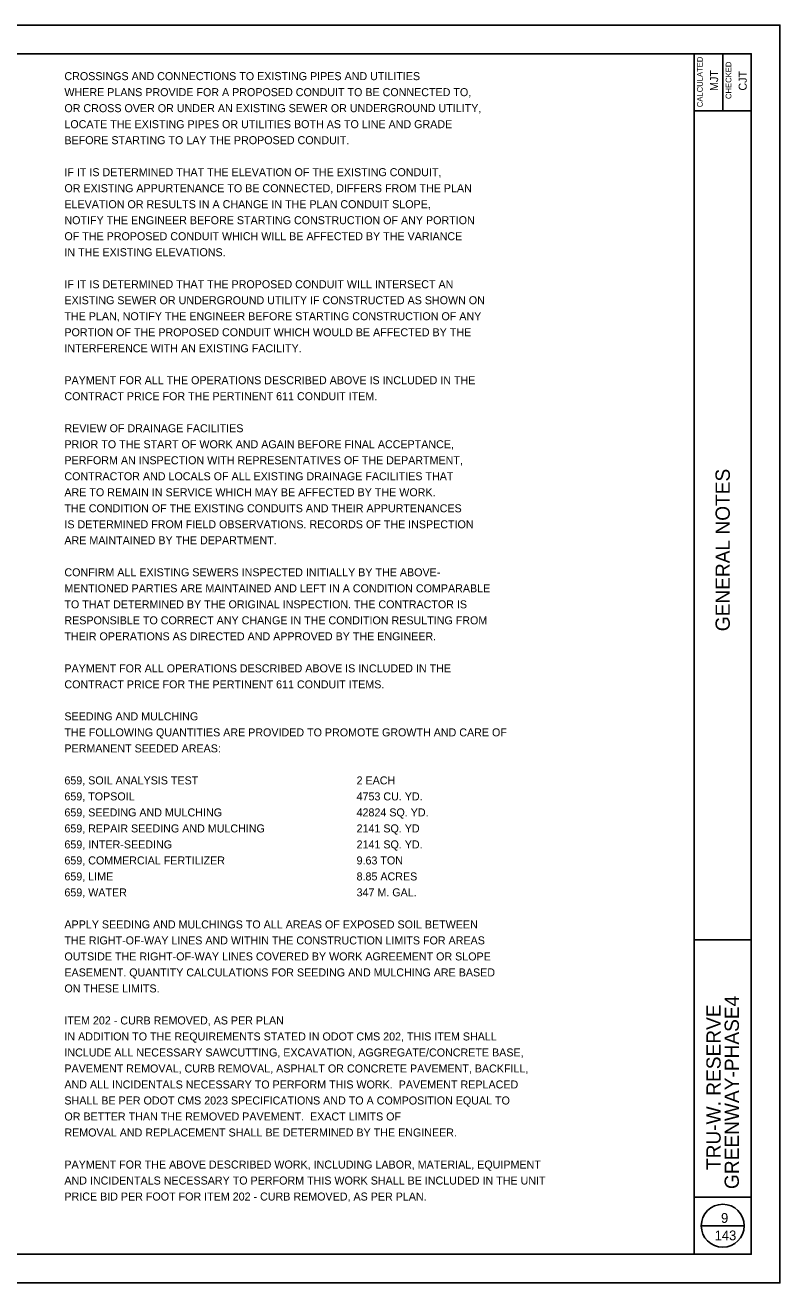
# Model space of a CAD drawing. Extents: x -16 to 195, y -13 to 9.
# Drawn here: x 4.43 to 17.63, y -12.91 to 9.09 of the extents above; entities that cross this region are included whole.
import ezdxf

# ---------------------------------------------------------------- set-up
doc = ezdxf.new("R2010")
doc.units = 0
for name, color, linetype in [('SH_Border', 7, 'Continuous'), ('SH_Cut_Line', 7, 'Continuous'), ('SH_Data', 7, 'Continuous'), ('TX_P_1', 7, 'Continuous')]:
    doc.layers.add(name, color=color, linetype=linetype)

msp = doc.modelspace()

# ---------------------------------------------------------------- linework, layer by layer
at = {"layer": 'SH_Border'}
for p, q in [((16.129, -12.407), (16.129, 8.593)), ((16.629, 8.593), (16.629, 7.593)), ((16.129, 7.593), (17.129, 7.593)), ((16.129, -6.907), (17.129, -6.907)), ((16.129, -11.407), (17.129, -11.407))]:
    msp.add_line(p, q, dxfattribs=at)
msp.add_lwpolyline([(-14.371, 8.593), (17.129, 8.593), (17.129, -12.407), (-14.371, -12.407)], close=True, dxfattribs=at)
at = {"layer": 'SH_Cut_Line'}
msp.add_lwpolyline([(-16.371, -12.907), (17.629, -12.907), (17.629, 9.093), (-16.371, 9.093)], close=True, dxfattribs=at)
at = {"layer": 'SH_Data'}
msp.add_line((16.254, -11.907), (17.004, -11.907), dxfattribs=at)
msp.add_circle((16.629, -11.907), 0.375, dxfattribs=at)

# ---------------------------------------------------------------- texts
for s, height, p in [('CALCULATED', 0.1, (16.281, 7.658)), ('CHECKED', 0.1, (16.781, 7.801)), ('MJT', 0.14, (16.549, 7.942)), ('CJT', 0.14, (17.049, 7.949)), ('GENERAL NOTES', 0.25, (16.754, -1.509)), ('GREENWAY-PHASE4', 0.25, (16.913, -11.266)), ('TRU-W. RESERVE', 0.25, (16.594, -10.934))]:
    msp.add_text(s, height=height, rotation=90, dxfattribs=at).set_placement(p)
for s, p in [('9', (16.6, -11.857)), ('143', (16.488, -12.162))]:
    msp.add_text(s, height=0.17, dxfattribs=at).set_placement(p)
at = {"layer": 'TX_P_1'}
for s, p in [('CROSSINGS AND CONNECTIONS TO EXISTING PIPES AND UTILITIES', (5.116, 8.131)), ('WHERE PLANS PROVIDE FOR A PROPOSED CONDUIT TO BE CONNECTED TO,', (5.116, 7.851)), ('OR CROSS OVER OR UNDER AN EXISTING SEWER OR UNDERGROUND UTILITY,', (5.116, 7.571)), ('LOCATE THE EXISTING PIPES OR UTILITIES BOTH AS TO LINE AND GRADE', (5.116, 7.291)), ('BEFORE STARTING TO LAY THE PROPOSED CONDUIT.', (5.116, 7.011)), ('IF IT IS DETERMINED THAT THE ELEVATION OF THE EXISTING CONDUIT,', (5.116, 6.451)), ('OR EXISTING APPURTENANCE TO BE CONNECTED, DIFFERS FROM THE PLAN', (5.116, 6.171)), ('ELEVATION OR RESULTS IN A CHANGE IN THE PLAN CONDUIT SLOPE,', (5.116, 5.891)), ('NOTIFY THE ENGINEER BEFORE STARTING CONSTRUCTION OF ANY PORTION', (5.116, 5.611)), ('OF THE PROPOSED CONDUIT WHICH WILL BE AFFECTED BY THE VARIANCE', (5.116, 5.331)), ('IN THE EXISTING ELEVATIONS.', (5.116, 5.051)), ('IF IT IS DETERMINED THAT THE PROPOSED CONDUIT WILL INTERSECT AN', (5.116, 4.491)), ('EXISTING SEWER OR UNDERGROUND UTILITY IF CONSTRUCTED AS SHOWN ON', (5.116, 4.211)), ('THE PLAN, NOTIFY THE ENGINEER BEFORE STARTING CONSTRUCTION OF ANY', (5.116, 3.931)), ('PORTION OF THE PROPOSED CONDUIT WHICH WOULD BE AFFECTED BY THE', (5.116, 3.651)), ('INTERFERENCE WITH AN EXISTING FACILITY.', (5.116, 3.371)), ('PAYMENT FOR ALL THE OPERATIONS DESCRIBED ABOVE IS INCLUDED IN THE', (5.116, 2.812)), ('CONTRACT PRICE FOR THE PERTINENT 611 CONDUIT ITEM.', (5.116, 2.532)), ('REVIEW OF DRAINAGE FACILITIES', (5.116, 1.972)), ('PRIOR TO THE START OF WORK AND AGAIN BEFORE FINAL ACCEPTANCE,', (5.116, 1.692)), ('PERFORM AN INSPECTION WITH REPRESENTATIVES OF THE DEPARTMENT,', (5.116, 1.412)), ('CONTRACTOR AND LOCALS OF ALL EXISTING DRAINAGE FACILITIES THAT', (5.116, 1.132)), ('ARE TO REMAIN IN SERVICE WHICH MAY BE AFFECTED BY THE WORK.', (5.116, 0.852)), ('THE CONDITION OF THE EXISTING CONDUITS AND THEIR APPURTENANCES', (5.116, 0.572)), ('IS DETERMINED FROM FIELD OBSERVATIONS. RECORDS OF THE INSPECTION', (5.116, 0.292)), ('ARE MAINTAINED BY THE DEPARTMENT.', (5.116, 0.012)), ('CONFIRM ALL EXISTING SEWERS INSPECTED INITIALLY BY THE ABOVE-', (5.116, -0.548)), ('MENTIONED PARTIES ARE MAINTAINED AND LEFT IN A CONDITION COMPARABLE', (5.116, -0.828)), ('TO THAT DETERMINED BY THE ORIGINAL INSPECTION. THE CONTRACTOR IS', (5.116, -1.108)), ('RESPONSIBLE TO CORRECT ANY CHANGE IN THE CONDITION RESULTING FROM', (5.116, -1.388)), ('THEIR OPERATIONS AS DIRECTED AND APPROVED BY THE ENGINEER.', (5.116, -1.668)), ('PAYMENT FOR ALL OPERATIONS DESCRIBED ABOVE IS INCLUDED IN THE', (5.116, -2.228)), ('CONTRACT PRICE FOR THE PERTINENT 611 CONDUIT ITEMS.', (5.116, -2.508)), ('SEEDING AND MULCHING', (5.116, -3.068)), ('THE FOLLOWING QUANTITIES ARE PROVIDED TO PROMOTE GROWTH AND CARE OF', (5.116, -3.348)), ('PERMANENT SEEDED AREAS:', (5.116, -3.628)), ('659, SOIL ANALYSIS TEST ', (5.116, -4.188)), ('2 EACH', (10.226, -4.188)), ('659, TOPSOIL ', (5.116, -4.468)), ('4753 CU. YD.', (10.226, -4.468)), ('659, SEEDING AND MULCHING', (5.116, -4.748)), ('42824 SQ. YD.', (10.226, -4.748)), ('659, REPAIR SEEDING AND MULCHING ', (5.116, -5.028)), ('2141 SQ. YD', (10.226, -5.028)), ('659, INTER-SEEDING ', (5.116, -5.308)), ('2141 SQ. YD.', (10.226, -5.308)), ('659, COMMERCIAL FERTILIZER ', (5.116, -5.588)), ('9.63 TON', (10.226, -5.588)), ('659, LIME ', (5.116, -5.868)), ('8.85 ACRES', (10.226, -5.868)), ('659, WATER ', (5.116, -6.147)), ('347 M. GAL.', (10.226, -6.147)), ('APPLY SEEDING AND MULCHINGS TO ALL AREAS OF EXPOSED SOIL BETWEEN', (5.116, -6.707)), ('THE RIGHT-OF-WAY LINES AND WITHIN THE CONSTRUCTION LIMITS FOR AREAS', (5.116, -6.987)), ('OUTSIDE THE RIGHT-OF-WAY LINES COVERED BY WORK AGREEMENT OR SLOPE', (5.116, -7.267)), ('EASEMENT. QUANTITY CALCULATIONS FOR SEEDING AND MULCHING ARE BASED', (5.116, -7.547)), ('ON THESE LIMITS.', (5.116, -7.827)), ('ITEM 202 - CURB REMOVED, AS PER PLAN', (5.116, -8.387)), ('IN ADDITION TO THE REQUIREMENTS STATED IN ODOT CMS 202, THIS ITEM SHALL', (5.116, -8.667)), ('INCLUDE ALL NECESSARY SAWCUTTING, EXCAVATION, AGGREGATE/CONCRETE BASE,', (5.116, -8.947)), ('PAVEMENT REMOVAL, CURB REMOVAL, ASPHALT OR CONCRETE PAVEMENT, BACKFILL,', (5.116, -9.227)), ('AND ALL INCIDENTALS NECESSARY TO PERFORM THIS WORK.  PAVEMENT REPLACED', (5.116, -9.507)), ('SHALL BE PER ODOT CMS 2023 SPECIFICATIONS AND TO A COMPOSITION EQUAL TO', (5.116, -9.787)), ('OR BETTER THAN THE REMOVED PAVEMENT.  EXACT LIMITS OF', (5.116, -10.067)), ('REMOVAL AND REPLACEMENT SHALL BE DETERMINED BY THE ENGINEER.', (5.116, -10.347)), ('PAYMENT FOR THE ABOVE DESCRIBED WORK, INCLUDING LABOR, MATERIAL, EQUIPMENT', (5.116, -10.907)), ('AND INCIDENTALS NECESSARY TO PERFORM THIS WORK SHALL BE INCLUDED IN THE UNIT', (5.116, -11.187)), ('PRICE BID PER FOOT FOR ITEM 202 - CURB REMOVED, AS PER PLAN.', (5.116, -11.467))]:
    msp.add_text(s, height=0.14, dxfattribs=at).set_placement(p)

doc.saveas('drawing.dxf')
